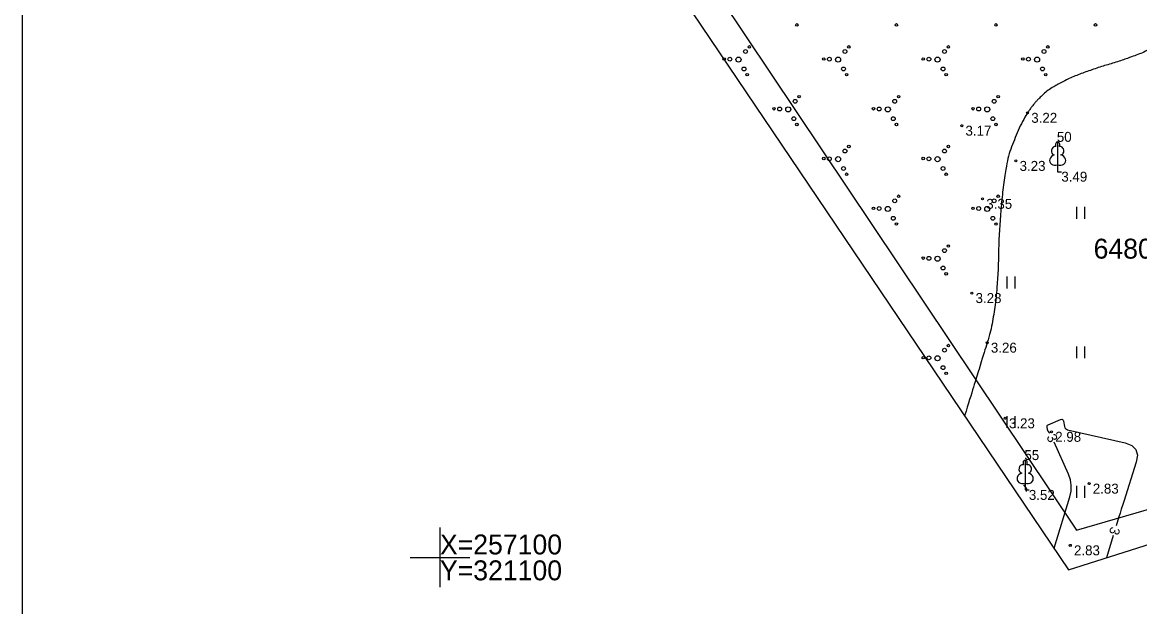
# Model space of a CAD drawing. Extents: x 321079 to 321220, y 257030 to 257220.
# Drawn here: x 321079 to 321135.2, y 257097.5 to 257126.9 of the extents above; entities that cross this region are included whole.
import ezdxf

# ---------------------------------------------------------------- set-up
doc = ezdxf.new("R2010")
doc.units = 0
for name, color, linetype in [('GEOD_ELEM_####_####_#', 7, 'Continuous'), ('GEOD_KORD_####_TKST_#', 7, 'Continuous'), ('RAMI_PLAN_####_TKST_#', 7, 'Continuous'), ('RAMI_UZMR_####_####_#', 7, 'Continuous'), ('RELJ_AATZ_####_TKST_#', 7, 'Continuous'), ('RELJ_ELEM_####_####_#', 7, 'Continuous'), ('RELJ_HORZ_####_TKST_#', 7, 'Continuous'), ('RELJ_HORZ_PAMT_####_#', 7, 'Continuous'), ('RELJ_HORZ_PUSH_####_#', 7, 'Continuous'), ('ROBZ_KADS_####_TKST_#', 7, 'Continuous'), ('ROBZ_UZMR_####_####_#', 7, 'Continuous'), ('TERT_DIAM_####_TKST_#', 7, 'Continuous'), ('TERT_ELEM_####_####_#', 7, 'Continuous'), ('TERT_KONT_####_####_#', 7, 'Continuous')]:
    doc.layers.add(name, color=color, linetype=linetype)

msp = doc.modelspace()

# ---------------------------------------------------------------- linework, layer by layer
at = {"layer": 'GEOD_ELEM_####_####_#'}
for p, q in [((321100, 257101.5), (321100, 257100)), ((321098.5, 257100), (321100, 257100)), ((321100, 257100), (321100, 257098.5)), ((321100, 257100), (321101.5, 257100))]:
    msp.add_line(p, q, dxfattribs=at)
at = {"layer": 'RAMI_PLAN_####_TKST_#'}
msp.add_lwpolyline([(321079.019, 257029.866), (321079.019, 257219.866), (321218.314, 257219.866), (321218.314, 257029.866)], close=True, dxfattribs=at)
at = {"layer": 'RAMI_UZMR_####_####_#'}
msp.add_lwpolyline([(321107.5, 257141.5), (321108.611, 257133.395), (321131.584, 257099.382), (321150.327, 257105.322), (321177.121, 257109.842), (321183.308, 257111.386), (321177.517, 257137.442), (321172.561, 257161.05), (321156.27, 257158.872), (321156.852, 257154.517), (321139.352, 257150.329), (321114.57, 257145.337)], close=True, dxfattribs=at)
at = {"layer": 'RELJ_ELEM_####_####_#'}
for centre in [(321129.524, 257122.327), (321126.218, 257121.682), (321128.937, 257119.913), (321127.263, 257118.007), (321126.726, 257113.275), (321127.494, 257110.784), (321128.402, 257106.986), (321130.727, 257106.307), (321132.615, 257103.705), (321131.67, 257100.606)]:
    msp.add_circle(centre, 0.05, dxfattribs=at)
at = {"layer": 'RELJ_HORZ_PAMT_####_#'}
for points in [[(321130.647, 257106.235), (321130.644, 257106.24), (321130.575, 257106.321), (321130.56, 257106.342), (321130.547, 257106.364), (321130.538, 257106.388), (321130.532, 257106.414), (321130.507, 257106.56), (321130.506, 257106.591), (321130.514, 257106.617), (321130.532, 257106.638), (321130.558, 257106.653), (321131.183, 257106.922), (321131.239, 257106.937), (321131.283, 257106.929), (321131.313, 257106.897), (321131.331, 257106.842), (321131.377, 257106.575), (321131.395, 257106.515), (321131.427, 257106.468), (321131.473, 257106.433), (321131.532, 257106.412), (321134.429, 257105.747), (321134.766, 257105.617), (321134.97, 257105.412), (321135.043, 257105.132), (321134.983, 257104.776), (321134.354, 257102.803), (321134.293, 257102.61), (321134.232, 257102.417), (321134.172, 257102.223), (321134.113, 257102.03), (321133.976, 257101.58)], [(321130.857, 257100.458), (321131.646, 257103.043), (321131.708, 257103.334), (321131.717, 257103.621), (321131.673, 257103.904), (321131.575, 257104.185), (321130.863, 257105.784)], [(321133.83, 257101.102), (321133.49, 257099.986)]]:
    msp.add_lwpolyline(points, dxfattribs=at)
at = {"layer": 'RELJ_HORZ_PUSH_####_#'}
msp.add_lwpolyline([(321129.469, 257103.308), (321129.489, 257103.376), (321129.492, 257103.387), (321129.492, 257103.398), (321129.49, 257103.409), (321129.487, 257103.42), (321129.463, 257103.472), (321129.457, 257103.484), (321129.45, 257103.496), (321129.443, 257103.507), (321129.435, 257103.518), (321129.334, 257103.637)], dxfattribs=at)
at = {"layer": 'ROBZ_UZMR_####_####_#'}
for p, q in [((321109.842, 257134.432), (321131.975, 257101.369)), ((321131.975, 257101.369), (321171.804, 257112.938))]:
    msp.add_line(p, q, dxfattribs=at)
at = {"layer": 'TERT_ELEM_####_####_#'}
for p, q in [((321131.034, 257119.718), (321131.034, 257119.371)), ((321131.034, 257119.371), (321131.234, 257119.371)), ((321132, 257117), (321132, 257117.6)), ((321132.4, 257117), (321132.4, 257117.6)), ((321128.5, 257113.5), (321128.5, 257114.1)), ((321128.9, 257113.5), (321128.9, 257114.1)), ((321132, 257110), (321132, 257110.6)), ((321132.4, 257110), (321132.4, 257110.6)), ((321128.5, 257106.5), (321128.5, 257107.1)), ((321128.9, 257106.5), (321128.9, 257107.1)), ((321129.403, 257103.736), (321129.403, 257103.389)), ((321129.403, 257103.389), (321129.603, 257103.389)), ((321132, 257103), (321132, 257103.6)), ((321132.4, 257103), (321132.4, 257103.6))]:
    msp.add_line(p, q, dxfattribs=at)
for points in [[(321131.034, 257120.871), (321131.034, 257119.718)], [(321131.124, 257120.639), (321131.123, 257120.64)], [(321129.403, 257104.889), (321129.403, 257103.736)], [(321129.493, 257104.657), (321129.492, 257104.658)]]:
    msp.add_lwpolyline(points, dxfattribs=at)
for centre, radius in [((321117.934, 257126.744), 0.064), ((321122.934, 257126.744), 0.064), ((321127.934, 257126.744), 0.064), ((321132.934, 257126.744), 0.064), ((321115.348, 257125.408), 0.096), ((321115.544, 257125.639), 0.064), ((321120.348, 257125.408), 0.096), ((321120.544, 257125.639), 0.064), ((321125.348, 257125.408), 0.096), ((321125.544, 257125.639), 0.064), ((321130.348, 257125.408), 0.096), ((321130.544, 257125.639), 0.064), ((321114.282, 257125.034), 0.064), ((321114.566, 257125.021), 0.096), ((321115, 257125), 0.128), ((321119.282, 257125.034), 0.064), ((321119.566, 257125.021), 0.096), ((321120, 257125), 0.128), ((321124.282, 257125.034), 0.064), ((321124.566, 257125.021), 0.096), ((321125, 257125), 0.128), ((321129.282, 257125.034), 0.064), ((321129.566, 257125.021), 0.096), ((321130, 257125), 0.128), ((321115.276, 257124.533), 0.096), ((321115.434, 257124.244), 0.064), ((321120.276, 257124.533), 0.096), ((321120.434, 257124.244), 0.064), ((321125.276, 257124.533), 0.096), ((321125.434, 257124.244), 0.064), ((321130.276, 257124.533), 0.096), ((321130.434, 257124.244), 0.064), ((321117.848, 257122.908), 0.096), ((321118.044, 257123.139), 0.064), ((321122.848, 257122.908), 0.096), ((321123.044, 257123.139), 0.064), ((321127.848, 257122.908), 0.096), ((321128.044, 257123.139), 0.064), ((321116.782, 257122.534), 0.064), ((321117.066, 257122.521), 0.096), ((321117.5, 257122.5), 0.128), ((321121.782, 257122.534), 0.064), ((321122.066, 257122.521), 0.096), ((321122.5, 257122.5), 0.128), ((321126.782, 257122.534), 0.064), ((321127.066, 257122.521), 0.096), ((321127.5, 257122.5), 0.128), ((321117.776, 257122.033), 0.096), ((321122.776, 257122.033), 0.096), ((321127.776, 257122.033), 0.096), ((321117.934, 257121.744), 0.064), ((321122.934, 257121.744), 0.064), ((321127.934, 257121.744), 0.064), ((321120.348, 257120.408), 0.096), ((321120.544, 257120.639), 0.064), ((321125.348, 257120.408), 0.096), ((321125.544, 257120.639), 0.064), ((321119.282, 257120.034), 0.064), ((321119.566, 257120.021), 0.096), ((321120, 257120), 0.128), ((321120.276, 257119.533), 0.096), ((321124.282, 257120.034), 0.064), ((321124.566, 257120.021), 0.096), ((321125, 257120), 0.128), ((321125.276, 257119.533), 0.096), ((321120.434, 257119.244), 0.064), ((321125.434, 257119.244), 0.064), ((321122.848, 257117.908), 0.096), ((321123.044, 257118.139), 0.064), ((321127.848, 257117.908), 0.096), ((321128.044, 257118.139), 0.064), ((321121.782, 257117.534), 0.064), ((321122.066, 257117.521), 0.096), ((321122.5, 257117.5), 0.128), ((321126.782, 257117.534), 0.064), ((321127.066, 257117.521), 0.096), ((321127.5, 257117.5), 0.128), ((321122.776, 257117.033), 0.096), ((321122.934, 257116.744), 0.064), ((321127.776, 257117.033), 0.096), ((321127.934, 257116.744), 0.064), ((321125.544, 257115.639), 0.064), ((321124.566, 257115.021), 0.096), ((321125, 257115), 0.128), ((321125.348, 257115.408), 0.096), ((321124.282, 257115.034), 0.064), ((321125.276, 257114.533), 0.096), ((321125.434, 257114.244), 0.064), ((321125.544, 257110.639), 0.064), ((321124.282, 257110.034), 0.064), ((321124.566, 257110.021), 0.096), ((321125, 257110), 0.128), ((321125.348, 257110.408), 0.096), ((321125.276, 257109.533), 0.096), ((321125.434, 257109.244), 0.064)]:
    msp.add_circle(centre, radius, dxfattribs=at)
for centre, major_axis, ratio, start_param, end_param in [((321131.034, 257120.721), (0, -0.15), 0.707107, 3.14537, 5.287485), ((321131.034, 257120.721), (0, -0.15), 0.707107, 0.995701, 3.137816), ((321130.944, 257119.964), (0.307, 0.095), 0.814445, 1.570796, 4.752015), ((321130.906, 257120.426), (-0.039, -0.212), 0.861323, 3.141593, 6.283185), ((321131.124, 257119.964), (-0.307, 0.095), 0.814445, 1.531171, 4.712389), ((321131.162, 257120.426), (0.039, -0.212), 0.861323, 0, 3.141593), ((321129.275, 257104.444), (-0.039, -0.212), 0.861323, 3.141593, 6.283185), ((321129.403, 257104.739), (0, -0.15), 0.707107, 3.14537, 5.287485), ((321129.403, 257104.739), (0, -0.15), 0.707107, 0.995701, 3.137816), ((321129.531, 257104.444), (0.039, -0.212), 0.861323, 0, 3.141593), ((321129.313, 257103.982), (0.307, 0.095), 0.814445, 1.570796, 4.752015), ((321129.493, 257103.982), (-0.307, 0.095), 0.814445, 1.531171, 4.712389)]:
    msp.add_ellipse(centre, major_axis=major_axis, ratio=ratio, start_param=start_param, end_param=end_param, dxfattribs=at)
at = {"layer": 'TERT_KONT_####_####_#'}
msp.add_open_spline([(321129.296, 257148.304), (321129.341, 257148.261), (321129.386, 257148.219), (321129.431, 257148.175), (321129.997, 257147.629), (321130.535, 257147.084), (321131.007, 257146.464), (321131.229, 257146.173), (321131.445, 257145.88), (321131.641, 257145.571), (321131.732, 257145.427), (321131.822, 257145.282), (321131.907, 257145.134), (321131.947, 257145.064), (321131.986, 257144.992), (321132.026, 257144.921), (321132.063, 257144.852), (321132.099, 257144.783), (321132.134, 257144.712), (321132.197, 257144.587), (321132.235, 257144.453), (321132.271, 257144.317), (321132.304, 257144.188), (321132.307, 257144.052), (321132.294, 257143.922), (321132.267, 257143.648), (321132.204, 257143.378), (321132.049, 257143.129), (321131.664, 257142.512), (321131.238, 257142.013), (321130.74, 257141.535), (321130.167, 257140.985), (321129.559, 257140.48), (321128.996, 257139.924), (321128.727, 257139.659), (321128.461, 257139.391), (321128.207, 257139.11), (321128.089, 257138.98), (321127.978, 257138.844), (321127.876, 257138.701), (321127.78, 257138.567), (321127.689, 257138.431), (321127.604, 257138.29), (321127.372, 257137.904), (321127.146, 257137.516), (321126.921, 257137.126), (321126.204, 257135.885), (321125.508, 257134.637), (321124.83, 257133.371), (321124.395, 257132.558), (321124.066, 257131.698), (321123.781, 257130.816), (321123.649, 257130.407), (321123.546, 257129.995), (321123.474, 257129.573), (321123.44, 257129.372), (321123.41, 257129.171), (321123.392, 257128.968), (321123.382, 257128.868), (321123.376, 257128.769), (321123.37, 257128.67), (321123.364, 257128.572), (321123.362, 257128.474), (321123.363, 257128.376), (321123.363, 257128.279), (321123.397, 257128.188), (321123.453, 257128.099), (321123.517, 257127.997), (321123.596, 257127.929), (321123.697, 257127.871), (321123.95, 257127.726), (321124.201, 257127.63), (321124.477, 257127.566), (321124.773, 257127.498), (321125.07, 257127.468), (321125.365, 257127.469), (321125.586, 257127.469), (321125.807, 257127.489), (321126.024, 257127.585), (321126.11, 257127.623), (321126.176, 257127.675), (321126.244, 257127.735), (321126.317, 257127.8), (321126.385, 257127.864), (321126.446, 257127.94), (321126.585, 257128.113), (321126.721, 257128.288), (321126.81, 257128.488), (321127.025, 257128.97), (321127.24, 257129.453), (321127.454, 257129.935), (321127.682, 257130.449), (321127.909, 257130.964), (321128.138, 257131.479), (321128.244, 257131.718), (321128.394, 257131.934), (321128.552, 257132.146), (321128.662, 257132.293), (321128.779, 257132.43), (321128.913, 257132.555), (321128.956, 257132.595), (321128.999, 257132.633), (321129.045, 257132.669), (321129.307, 257132.877), (321129.57, 257133.08), (321129.838, 257133.28), (321130.141, 257133.505), (321130.45, 257133.717), (321130.763, 257133.93), (321131.417, 257134.374), (321132.085, 257134.734), (321132.823, 257135.088), (321133.478, 257135.403), (321134.165, 257135.57), (321134.85, 257135.629), (321135.141, 257135.654), (321135.444, 257135.606), (321135.734, 257135.506), (321135.875, 257135.457), (321136.001, 257135.399), (321136.124, 257135.317), (321136.251, 257135.233), (321136.366, 257135.144), (321136.47, 257135.034), (321136.693, 257134.798), (321136.896, 257134.556), (321137.073, 257134.288), (321137.256, 257134.01), (321137.432, 257133.732), (321137.583, 257133.438), (321137.739, 257133.135), (321137.891, 257132.832), (321138.033, 257132.524), (321138.177, 257132.212), (321138.309, 257131.894), (321138.456, 257131.583), (321138.59, 257131.301), (321138.733, 257131.023), (321138.869, 257130.742), (321139.009, 257130.456), (321139.139, 257130.17), (321139.267, 257129.874), (321139.384, 257129.605), (321139.444, 257129.316), (321139.472, 257129.03), (321139.485, 257128.899), (321139.474, 257128.764), (321139.446, 257128.633), (321139.433, 257128.568), (321139.415, 257128.506), (321139.391, 257128.443), (321139.367, 257128.38), (321139.34, 257128.32), (321139.305, 257128.261), (321139.147, 257127.999), (321138.966, 257127.764), (321138.743, 257127.556), (321138.511, 257127.34), (321138.274, 257127.139), (321138.012, 257126.967), (321137.742, 257126.789), (321137.472, 257126.612), (321137.197, 257126.441), (321137.059, 257126.356), (321136.921, 257126.272), (321136.784, 257126.186), (321136.648, 257126.102), (321136.516, 257126.013), (321136.381, 257125.928), (321136.104, 257125.753), (321135.818, 257125.594), (321135.521, 257125.454), (321135.219, 257125.311), (321134.907, 257125.196), (321134.594, 257125.083), (321133.961, 257124.856), (321133.312, 257124.683), (321132.677, 257124.46), (321132.063, 257124.245), (321131.471, 257123.99), (321130.897, 257123.67), (321130.617, 257123.514), (321130.371, 257123.316), (321130.143, 257123.092), (321130.026, 257122.978), (321129.916, 257122.862), (321129.814, 257122.736), (321129.763, 257122.671), (321129.713, 257122.606), (321129.664, 257122.538), (321129.615, 257122.47), (321129.568, 257122.4), (321129.524, 257122.327), (321129.259, 257121.895), (321129.047, 257121.444), (321128.858, 257120.971), (321128.674, 257120.511), (321128.527, 257120.045), (321128.449, 257119.559), (321128.293, 257118.586), (321128.187, 257117.612), (321128.124, 257116.631), (321128.06, 257115.644), (321128.061, 257114.653), (321127.991, 257113.666), (321127.956, 257113.177), (321127.906, 257112.691), (321127.823, 257112.207), (321127.74, 257111.725), (321127.638, 257111.249), (321127.494, 257110.784), (321127.116, 257109.561), (321126.739, 257108.338), (321126.361, 257107.115)], degree=3, dxfattribs=at)

# ---------------------------------------------------------------- texts
at = {"layer": 'GEOD_KORD_####_TKST_#'}
for s, p in [('X=257100', (321100, 257100.15)), ('Y=321100', (321100, 257098.85))]:
    msp.add_text(s, height=1, dxfattribs=at).set_placement(p)
at = {"layer": 'RELJ_AATZ_####_TKST_#'}
for s, p in [(' 3.22', (321129.524, 257121.827)), (' 3.17', (321126.218, 257121.182)), (' 3.23', (321128.937, 257119.413)), (' 3.49', (321131.034, 257118.871)), (' 3.35', (321127.263, 257117.507)), (' 3.28', (321126.726, 257112.775)), (' 3.26', (321127.494, 257110.284)), (' 3.23', (321128.402, 257106.486)), (' 2.98', (321130.727, 257105.807)), (' 3.52', (321129.403, 257102.889)), (' 2.83', (321132.615, 257103.205)), (' 2.83', (321131.67, 257100.106))]:
    msp.add_text(s, height=0.5, dxfattribs=at).set_placement(p)
at = {"layer": 'RELJ_HORZ_####_TKST_#'}
for rotation, p in [(295.5373, (321130.457, 257106.053)), (253.0416, (321133.713, 257101.575))]:
    msp.add_text('3', height=0.5, rotation=rotation, dxfattribs=at).set_placement(p)
at = {"layer": 'ROBZ_KADS_####_TKST_#'}
msp.add_text('64800030132', height=1, dxfattribs=at).set_placement((321132.84, 257115.006))
at = {"layer": 'TERT_DIAM_####_TKST_#'}
for s, p in [(' 50', (321130.809, 257120.871)), (' 55', (321129.178, 257104.889))]:
    msp.add_text(s, height=0.5, dxfattribs=at).set_placement(p)

doc.saveas('drawing.dxf')
